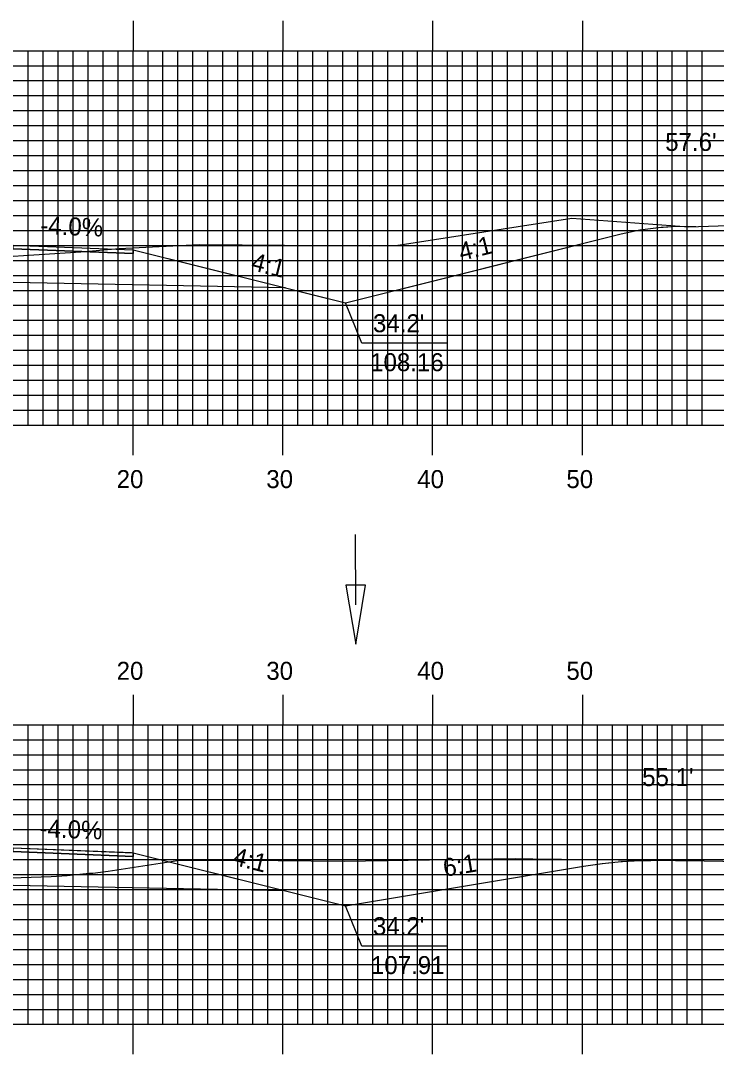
# Model space of a CAD drawing. Extents: x 1766120 to 1766463, y 442591 to 442811.
# Drawn here: x 1766297.9 to 1766344.3, y 442691.7 to 442760.7 of the extents above; entities that cross this region are included whole.
import ezdxf

# ---------------------------------------------------------------- set-up
doc = ezdxf.new("R2010")
doc.units = 0
for name, color, linetype in [('ANNOTATION', 7, 'Continuous'), ('D_Drainage_Ditch_Line', 7, 'Continuous'), ('D_Roadway_Centerline', 7, 'Continuous'), ('D_Roadway_Edge_Shoulder', 7, 'Continuous'), ('D_Roadway_SlopeLines', 7, 'Continuous'), ('D_Roadway_SubGrade', 7, 'Continuous'), ('D_Text_Standard', 7, 'Continuous'), ('H_V ANNOTATION', 7, 'Continuous'), ('MAJOR', 7, 'Continuous'), ('MINOR', 7, 'Continuous'), ('S_Roadway_Centerline', 7, 'Continuous')]:
    doc.layers.add(name, color=color, linetype=linetype)

msp = doc.modelspace()

# ---------------------------------------------------------------- linework, layer by layer
at = {"layer": 'ANNOTATION'}
for points in [[(1766326.371, 442739.143), (1766320.679, 442739.143), (1766319.572, 442741.828)], [(1766326.37, 442698.893), (1766320.678, 442698.893), (1766319.571, 442701.578)]]:
    msp.add_lwpolyline(points, dxfattribs=at)
at = {"layer": 'D_Drainage_Ditch_Line'}
msp.add_line((1766320.26, 442721.659), (1766320.259, 442726.358), dxfattribs=at)
msp.add_lwpolyline([(1766320.916, 442722.972), (1766319.603, 442722.972), (1766320.26, 442719.035)], close=True, dxfattribs=at)
at = {"layer": 'D_Roadway_Centerline'}
for points in [[(1766251.223, 442742.356), (1766255.058, 442743.315), (1766255.223, 442743.356), (1766265.397, 442745.9), (1766273.397, 442746.22), (1766279.088, 442746.095), (1766285.397, 442745.956), (1766285.4, 442745.956), (1766297.397, 442745.692), (1766305.397, 442745.372), (1766305.398, 442745.372), (1766309.87, 442744.254), (1766315.571, 442742.828), (1766317.332, 442742.388), (1766319.572, 442741.828), (1766327.356, 442743.774), (1766337.977, 442746.429), (1766339.227, 442746.695), (1766340.477, 442746.865), (1766340.646, 442746.875), (1766341.727, 442746.941), (1766342.638, 442746.928), (1766342.977, 442746.923)], [(1766297.399, 442705.442), (1766305.297, 442705.126), (1766305.398, 442705.122), (1766315.572, 442702.578), (1766319.571, 442701.578), (1766335.476, 442704.229), (1766336.726, 442704.409), (1766337.975, 442704.534), (1766338.074, 442704.54), (1766339.226, 442704.604), (1766339.96, 442704.612), (1766340.476, 442704.617)]]:
    msp.add_lwpolyline(points, dxfattribs=at)
at = {"layer": 'D_Roadway_Edge_Shoulder'}
for points in [[(1766297.397, 442745.692), (1766305.397, 442745.372), (1766305.397, 442745.122), (1766297.397, 442745.442)], [(1766297.397, 442705.442), (1766305.398, 442705.122), (1766305.398, 442704.872), (1766297.397, 442705.192)]]:
    msp.add_lwpolyline(points, close=True, dxfattribs=at)
at = {"layer": 'D_Roadway_SlopeLines'}
for points in [[(1766319.572, 442741.828), (1766337.976, 442746.429), (1766339.227, 442746.695), (1766340.477, 442746.865), (1766341.727, 442746.941), (1766342.976, 442746.923)], [(1766305.397, 442745.372), (1766319.572, 442741.828)], [(1766305.398, 442705.122), (1766319.571, 442701.578)], [(1766319.571, 442701.578), (1766335.476, 442704.229), (1766336.725, 442704.409), (1766337.975, 442704.534), (1766339.226, 442704.604), (1766340.476, 442704.617)]]:
    msp.add_lwpolyline(points, dxfattribs=at)
at = {"layer": 'D_Roadway_SubGrade'}
for points in [[(1766273.397, 442743.72), (1766255.223, 442743.356), (1766265.397, 442745.9), (1766265.397, 442745.65), (1766273.397, 442745.97), (1766285.397, 442745.706), (1766297.397, 442745.442), (1766305.397, 442745.122), (1766305.397, 442745.372), (1766315.571, 442742.828), (1766297.397, 442743.192), (1766285.397, 442743.456)], [(1766273.397, 442703.47), (1766255.223, 442703.106), (1766265.397, 442705.65), (1766265.397, 442705.4), (1766273.397, 442705.72), (1766285.397, 442705.456), (1766297.397, 442705.192), (1766305.398, 442704.872), (1766305.398, 442705.122), (1766315.571, 442702.578), (1766297.397, 442702.942), (1766285.397, 442703.206)]]:
    msp.add_lwpolyline(points, close=True, dxfattribs=at)
at = {"layer": 'MAJOR'}
for p, q in [((1766305.397, 442760.669), (1766305.397, 442758.665)), ((1766315.397, 442760.669), (1766315.397, 442758.665)), ((1766325.397, 442760.669), (1766325.397, 442758.665)), ((1766335.397, 442760.669), (1766335.397, 442758.665)), ((1766145.397, 442758.665), (1766425.397, 442758.665)), ((1766145.397, 442758.665), (1766425.397, 442758.665)), ((1766305.397, 442733.665), (1766305.397, 442758.665)), ((1766315.397, 442733.665), (1766315.397, 442758.665)), ((1766325.397, 442733.665), (1766325.397, 442758.665)), ((1766335.397, 442733.665), (1766335.397, 442758.665)), ((1766145.397, 442753.665), (1766425.397, 442753.665)), ((1766145.397, 442748.665), (1766425.397, 442748.665)), ((1766145.397, 442743.665), (1766425.397, 442743.665)), ((1766145.397, 442738.665), (1766425.397, 442738.665)), ((1766145.397, 442733.665), (1766425.397, 442733.665)), ((1766145.397, 442733.665), (1766425.397, 442733.665)), ((1766305.397, 442731.661), (1766305.397, 442733.665)), ((1766315.397, 442731.661), (1766315.397, 442733.665)), ((1766325.397, 442731.661), (1766325.397, 442733.665)), ((1766335.397, 442731.661), (1766335.397, 442733.665)), ((1766305.397, 442715.669), (1766305.397, 442713.665)), ((1766315.397, 442715.669), (1766315.397, 442713.665)), ((1766325.397, 442715.669), (1766325.397, 442713.665)), ((1766335.397, 442715.669), (1766335.397, 442713.665)), ((1766145.397, 442713.665), (1766425.397, 442713.665)), ((1766145.397, 442713.665), (1766425.397, 442713.665)), ((1766305.397, 442693.665), (1766305.397, 442713.665)), ((1766315.397, 442693.665), (1766315.397, 442713.665)), ((1766325.397, 442693.665), (1766325.397, 442713.665)), ((1766335.397, 442693.665), (1766335.397, 442713.665)), ((1766145.397, 442708.665), (1766425.397, 442708.665)), ((1766145.397, 442703.665), (1766425.397, 442703.665)), ((1766145.397, 442698.665), (1766425.397, 442698.665)), ((1766145.397, 442693.665), (1766425.397, 442693.665)), ((1766145.397, 442693.665), (1766425.397, 442693.665)), ((1766305.397, 442691.661), (1766305.397, 442693.665)), ((1766315.397, 442691.661), (1766315.397, 442693.665)), ((1766325.397, 442691.661), (1766325.397, 442693.665)), ((1766335.397, 442691.661), (1766335.397, 442693.665))]:
    msp.add_line(p, q, dxfattribs=at)
at = {"layer": 'MINOR'}
for p, q in [((1766298.397, 442733.665), (1766298.397, 442758.665)), ((1766299.397, 442733.665), (1766299.397, 442758.665)), ((1766300.397, 442733.665), (1766300.397, 442758.665)), ((1766301.397, 442733.665), (1766301.397, 442758.665)), ((1766302.397, 442733.665), (1766302.397, 442758.665)), ((1766303.397, 442733.665), (1766303.397, 442758.665)), ((1766304.397, 442733.665), (1766304.397, 442758.665)), ((1766306.397, 442733.665), (1766306.397, 442758.665)), ((1766307.397, 442733.665), (1766307.397, 442758.665)), ((1766308.397, 442733.665), (1766308.397, 442758.665)), ((1766309.397, 442733.665), (1766309.397, 442758.665)), ((1766310.397, 442733.665), (1766310.397, 442758.665)), ((1766311.397, 442733.665), (1766311.397, 442758.665)), ((1766312.397, 442733.665), (1766312.397, 442758.665)), ((1766313.397, 442733.665), (1766313.397, 442758.665)), ((1766314.397, 442733.665), (1766314.397, 442758.665)), ((1766316.397, 442733.665), (1766316.397, 442758.665)), ((1766317.397, 442733.665), (1766317.397, 442758.665)), ((1766318.397, 442733.665), (1766318.397, 442758.665)), ((1766319.397, 442733.665), (1766319.397, 442758.665)), ((1766320.397, 442733.665), (1766320.397, 442758.665)), ((1766321.397, 442733.665), (1766321.397, 442758.665)), ((1766322.397, 442733.665), (1766322.397, 442758.665)), ((1766323.397, 442733.665), (1766323.397, 442758.665)), ((1766324.397, 442733.665), (1766324.397, 442758.665)), ((1766326.397, 442733.665), (1766326.397, 442758.665)), ((1766327.397, 442733.665), (1766327.397, 442758.665)), ((1766328.397, 442733.665), (1766328.397, 442758.665)), ((1766329.397, 442733.665), (1766329.397, 442758.665)), ((1766330.397, 442733.665), (1766330.397, 442758.665)), ((1766331.397, 442733.665), (1766331.397, 442758.665)), ((1766332.397, 442733.665), (1766332.397, 442758.665)), ((1766333.397, 442733.665), (1766333.397, 442758.665)), ((1766334.397, 442733.665), (1766334.397, 442758.665)), ((1766336.397, 442733.665), (1766336.397, 442758.665)), ((1766337.397, 442733.665), (1766337.397, 442758.665)), ((1766338.397, 442733.665), (1766338.397, 442758.665)), ((1766339.397, 442733.665), (1766339.397, 442758.665)), ((1766340.397, 442733.665), (1766340.397, 442758.665)), ((1766341.397, 442733.665), (1766341.397, 442758.665)), ((1766342.397, 442733.665), (1766342.397, 442758.665)), ((1766343.397, 442733.665), (1766343.397, 442758.665)), ((1766145.397, 442757.665), (1766425.397, 442757.665)), ((1766145.397, 442756.665), (1766425.397, 442756.665)), ((1766145.397, 442755.665), (1766425.397, 442755.665)), ((1766145.397, 442754.665), (1766425.397, 442754.665)), ((1766145.397, 442752.665), (1766425.397, 442752.665)), ((1766145.397, 442751.665), (1766425.397, 442751.665)), ((1766145.397, 442750.665), (1766425.397, 442750.665)), ((1766145.397, 442749.665), (1766425.397, 442749.665)), ((1766145.397, 442747.665), (1766425.397, 442747.665)), ((1766145.397, 442746.665), (1766425.397, 442746.665)), ((1766145.397, 442745.665), (1766425.397, 442745.665)), ((1766145.397, 442744.665), (1766425.397, 442744.665)), ((1766145.397, 442742.665), (1766425.397, 442742.665)), ((1766145.397, 442741.665), (1766425.397, 442741.665)), ((1766145.397, 442740.665), (1766425.397, 442740.665)), ((1766145.397, 442739.665), (1766425.397, 442739.665)), ((1766145.397, 442737.665), (1766425.397, 442737.665)), ((1766145.397, 442736.665), (1766425.397, 442736.665)), ((1766145.397, 442735.665), (1766425.397, 442735.665)), ((1766145.397, 442734.665), (1766425.397, 442734.665)), ((1766298.397, 442693.665), (1766298.397, 442713.665)), ((1766299.397, 442693.665), (1766299.397, 442713.665)), ((1766300.397, 442693.665), (1766300.397, 442713.665)), ((1766301.397, 442693.665), (1766301.397, 442713.665)), ((1766302.397, 442693.665), (1766302.397, 442713.665)), ((1766303.397, 442693.665), (1766303.397, 442713.665)), ((1766304.397, 442693.665), (1766304.397, 442713.665)), ((1766306.397, 442693.665), (1766306.397, 442713.665)), ((1766307.397, 442693.665), (1766307.397, 442713.665)), ((1766308.397, 442693.665), (1766308.397, 442713.665)), ((1766309.397, 442693.665), (1766309.397, 442713.665)), ((1766310.397, 442693.665), (1766310.397, 442713.665)), ((1766311.397, 442693.665), (1766311.397, 442713.665)), ((1766312.397, 442693.665), (1766312.397, 442713.665)), ((1766313.397, 442693.665), (1766313.397, 442713.665)), ((1766314.397, 442693.665), (1766314.397, 442713.665)), ((1766316.397, 442693.665), (1766316.397, 442713.665)), ((1766317.397, 442693.665), (1766317.397, 442713.665)), ((1766318.397, 442693.665), (1766318.397, 442713.665)), ((1766319.397, 442693.665), (1766319.397, 442713.665)), ((1766320.397, 442693.665), (1766320.397, 442713.665)), ((1766321.397, 442693.665), (1766321.397, 442713.665)), ((1766322.397, 442693.665), (1766322.397, 442713.665)), ((1766323.397, 442693.665), (1766323.397, 442713.665)), ((1766324.397, 442693.665), (1766324.397, 442713.665)), ((1766326.397, 442693.665), (1766326.397, 442713.665)), ((1766327.397, 442693.665), (1766327.397, 442713.665)), ((1766328.397, 442693.665), (1766328.397, 442713.665)), ((1766329.397, 442693.665), (1766329.397, 442713.665)), ((1766330.397, 442693.665), (1766330.397, 442713.665)), ((1766331.397, 442693.665), (1766331.397, 442713.665)), ((1766332.397, 442693.665), (1766332.397, 442713.665)), ((1766333.397, 442693.665), (1766333.397, 442713.665)), ((1766334.397, 442693.665), (1766334.397, 442713.665)), ((1766336.397, 442693.665), (1766336.397, 442713.665)), ((1766337.397, 442693.665), (1766337.397, 442713.665)), ((1766338.397, 442693.665), (1766338.397, 442713.665)), ((1766339.397, 442693.665), (1766339.397, 442713.665)), ((1766340.397, 442693.665), (1766340.397, 442713.665)), ((1766341.397, 442693.665), (1766341.397, 442713.665)), ((1766342.397, 442693.665), (1766342.397, 442713.665)), ((1766343.397, 442693.665), (1766343.397, 442713.665)), ((1766145.397, 442712.665), (1766425.397, 442712.665)), ((1766145.397, 442711.665), (1766425.397, 442711.665)), ((1766145.397, 442710.665), (1766425.397, 442710.665)), ((1766145.397, 442709.665), (1766425.397, 442709.665)), ((1766145.397, 442707.665), (1766425.397, 442707.665)), ((1766145.397, 442706.665), (1766425.397, 442706.665)), ((1766145.397, 442705.665), (1766425.397, 442705.665)), ((1766145.397, 442704.665), (1766425.397, 442704.665)), ((1766145.397, 442702.665), (1766425.397, 442702.665)), ((1766145.397, 442701.665), (1766425.397, 442701.665)), ((1766145.397, 442700.665), (1766425.397, 442700.665)), ((1766145.397, 442699.665), (1766425.397, 442699.665)), ((1766145.397, 442697.665), (1766425.397, 442697.665)), ((1766145.397, 442696.665), (1766425.397, 442696.665)), ((1766145.397, 442695.665), (1766425.397, 442695.665)), ((1766145.397, 442694.665), (1766425.397, 442694.665))]:
    msp.add_line(p, q, dxfattribs=at)
at = {"layer": 'S_Roadway_Centerline'}
for points in [[(1766230.934, 442745.727), (1766247.306, 442745.697), (1766248.608, 442745.665), (1766249.719, 442745.639), (1766261.776, 442745.249), (1766267.937, 442744.933), (1766276.398, 442744.454), (1766284.342, 442744.246), (1766286.107, 442744.222), (1766291.11, 442744.614), (1766294.984, 442744.807), (1766296.097, 442744.875), (1766296.259, 442744.891), (1766296.326, 442744.889), (1766301.922, 442745.235), (1766304.461, 442745.468), (1766309.829, 442745.727), (1766321.206, 442745.648), (1766322.403, 442745.653), (1766322.934, 442745.654), (1766334.699, 442747.48), (1766342.489, 442746.906), (1766346.419, 442747.042)], [(1766294.589, 442703.353), (1766299.93, 442703.542), (1766301.001, 442703.608), (1766302.475, 442703.75), (1766302.711, 442703.745), (1766303.746, 442703.885), (1766308.366, 442704.612), (1766312.883, 442704.621), (1766319.499, 442704.552), (1766330.896, 442704.724), (1766332.077, 442704.712), (1766343.526, 442704.583), (1766349.786, 442704.472)]]:
    msp.add_lwpolyline(points, dxfattribs=at)

# ---------------------------------------------------------------- texts
at = {"layer": 'ANNOTATION'}
for s, rotation, p in [('-4.0%', 357.70939, (1766299.189, 442746.422)), ('4:1', 14.03554, (1766327.31, 442744.624)), ('4:1', 345.96127, (1766313.215, 442744.037)), ('-4.0%', 357.70955, (1766299.14, 442706.174)), ('4:1', 345.96129, (1766311.99, 442704.335)), ('6:1', 9.46301, (1766326.199, 442703.511))]:
    msp.add_text(s, height=1.2, rotation=rotation, dxfattribs=at).set_placement(p)
for s, p in [("34.2'", (1766321.414, 442739.869)), ('108.16', (1766321.226, 442737.269)), ("34.2'", (1766321.413, 442699.619)), ('107.91', (1766321.279, 442697.019))]:
    msp.add_text(s, height=1.2, dxfattribs=at).set_placement(p)
at = {"layer": 'D_Text_Standard'}
for s, p in [("57.6'", (1766340.923, 442751.974)), ("55.1'", (1766339.384, 442709.568))]:
    msp.add_text(s, height=1.2, dxfattribs=at).set_placement(p)
at = {"layer": 'H_V ANNOTATION'}
for s, p in [('20', (1766304.305, 442729.465)), ('30', (1766314.294, 442729.465)), ('40', (1766324.369, 442729.465)), ('50', (1766334.326, 442729.465)), ('20', (1766304.305, 442716.665)), ('30', (1766314.294, 442716.665)), ('40', (1766324.369, 442716.665)), ('50', (1766334.326, 442716.665))]:
    msp.add_text(s, height=1.2, dxfattribs=at).set_placement(p)

doc.saveas('drawing.dxf')
